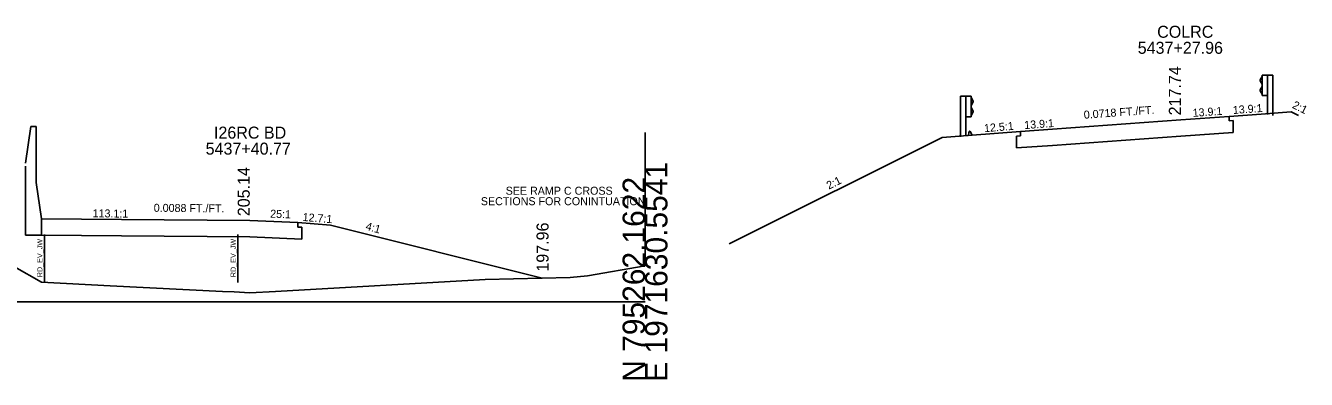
# Model space of a CAD drawing. Extents: x -161 to 1970889, y -4362 to 797231.
# Drawn here: x 1222.6 to 1382.7, y 3990.3 to 4034.5 of the extents above; entities that cross this region are included whole.
import ezdxf

# ---------------------------------------------------------------- set-up
doc = ezdxf.new("R2010")
doc.units = 0
for name, color, linetype in [('RD_GPK_XS_Cell', 7, 'Continuous'), ('RD_XS_Base', 7, 'Continuous'), ('RD_XS_CurbTop', 7, 'Continuous'), ('RD_XS_EarthShd', 7, 'Continuous'), ('RD_XS_ExGround', 7, 'Continuous'), ('RD_XS_EXWetland', 7, 'Continuous'), ('RD_XS_GR', 7, 'Continuous'), ('RD_XS_MedBWall', 7, 'Continuous'), ('RD_XS_Pave', 7, 'Continuous'), ('RD_XS_PaveShd', 7, 'Continuous'), ('RD_XS_TieSlope', 7, 'Continuous'), ('RD_XS_TX_Elev_PR', 7, 'Continuous'), ('RD_XS_TX_Misc', 7, 'Continuous'), ('RD_XS_TX_Notes', 7, 'Continuous'), ('RD_XS_TX_Profile', 7, 'Continuous'), ('RD_XS_TX_ShdSlope', 7, 'Continuous'), ('RD_XS_TX_Slope', 7, 'Continuous'), ('RD_XS_TX_Station', 7, 'Continuous')]:
    doc.layers.add(name, color=color, linetype=linetype)

msp = doc.modelspace()

# ---------------------------------------------------------------- linework, layer by layer
at = {"layer": 'RD_GPK_XS_Cell'}
msp.add_line((1150, 4000), (1300, 4000), dxfattribs=at)
at = {"layer": 'RD_XS_Base'}
for p, q in [((1372.99, 4022.61), (1372.99, 4023.17)), ((1346.92, 4020.73), (1346.92, 4021.29)), ((1373.49, 4022.65), (1372.99, 4022.61)), ((1373.49, 4021.17), (1373.49, 4022.65)), ((1346.42, 4020.7), (1346.92, 4020.73)), ((1346.42, 4019.22), (1346.42, 4020.7)), ((1350.93, 4019.54), (1366.97, 4020.7)), ((1366.97, 4020.7), (1373.49, 4021.17)), ((1350.93, 4019.54), (1346.42, 4019.22)), ((1224.58, 4009.81), (1224.58, 4010.37)), ((1256.59, 4009.34), (1256.59, 4009.9)), ((1257.09, 4009.32), (1256.59, 4009.34)), ((1257.09, 4007.84), (1257.09, 4009.32)), ((1234.58, 4008.24), (1224.58, 4008.33)), ((1234.58, 4008.24), (1250.59, 4008.1)), ((1250.59, 4008.1), (1257.09, 4007.84))]:
    msp.add_line(p, q, dxfattribs=at)
at = {"layer": 'RD_XS_CurbTop'}
for p, q in [((1340.9, 4020.81), (1340.65, 4021.27)), ((1340.43, 4020.78), (1340.49, 4021.21)), ((1340.9, 4020.81), (1340.43, 4020.78))]:
    msp.add_line(p, q, dxfattribs=at)
msp.add_ellipse((1340.58, 4021.19), major_axis=(0, 0.131), ratio=0.686, start_param=5.388101, end_param=7.661995, dxfattribs=at)
at = {"layer": 'RD_XS_EarthShd'}
for p, q in [((1372.99, 4023.17), (1377, 4023.46)), ((1346.92, 4021.29), (1340.9, 4020.81)), ((1256.59, 4009.9), (1260.67, 4009.58))]:
    msp.add_line(p, q, dxfattribs=at)
at = {"layer": 'RD_XS_ExGround'}
msp.add_lwpolyline([(1217.76, 4006.3), (1224.56, 4002.45), (1233.16, 4002.01), (1247.17, 4001.3), (1248.66, 4001.24), (1250.61, 4001.14), (1253.83, 4001.27), (1280.03, 4002.78), (1290.63, 4003.05), (1292.82, 4003.25), (1300, 4004.49)], dxfattribs=at)
at = {"layer": 'RD_XS_EXWetland'}
for p, q in [((1224.93, 4008.43), (1224.93, 4002.43)), ((1249.1, 4008.43), (1249.1, 4002.43))]:
    msp.add_line(p, q, dxfattribs=at)
at = {"layer": 'RD_XS_GR'}
for p, q in [((1377.15, 4028.17), (1376.88, 4027.73)), ((1376.88, 4027.73), (1376.88, 4027.62)), ((1377.15, 4028.33), (1377.81, 4028.33)), ((1377.15, 4025.76), (1377.15, 4028.33)), ((1377.81, 4028.33), (1378.48, 4028.33)), ((1377.81, 4028.33), (1377.81, 4023.39)), ((1378.48, 4028.33), (1378.48, 4023.28)), ((1376.88, 4027.62), (1377.15, 4027.18)), ((1376.88, 4026.48), (1377.15, 4026.92)), ((1376.88, 4026.37), (1376.88, 4026.48)), ((1377.15, 4025.93), (1376.88, 4026.37)), ((1340.09, 4025.69), (1339.42, 4025.69)), ((1339.42, 4025.69), (1339.42, 4020.63)), ((1340.75, 4025.69), (1340.09, 4025.69)), ((1340.09, 4025.69), (1340.09, 4020.75)), ((1340.75, 4023.12), (1340.75, 4025.69)), ((1340.75, 4025.53), (1341.02, 4025.09)), ((1341.02, 4024.98), (1340.75, 4024.54)), ((1341.02, 4025.09), (1341.02, 4024.98)), ((1377.15, 4025.76), (1377.81, 4025.76)), ((1340.75, 4023.12), (1340.09, 4023.12)), ((1341.02, 4023.83), (1340.75, 4024.27)), ((1340.75, 4023.28), (1341.02, 4023.72)), ((1341.02, 4023.72), (1341.02, 4023.83))]:
    msp.add_line(p, q, dxfattribs=at)
at = {"layer": 'RD_XS_MedBWall'}
for p, q in [((1222.58, 4017.34), (1223.25, 4021.89)), ((1223.91, 4021.89), (1223.25, 4021.89)), ((1223.91, 4021.89), (1223.91, 4014.92)), ((1222.58, 4016.94), (1222.58, 4008.33)), ((1224.58, 4010.37), (1223.91, 4014.92)), ((1224.58, 4010.37), (1224.58, 4008.33)), ((1224.58, 4008.33), (1222.58, 4008.33))]:
    msp.add_line(p, q, dxfattribs=at)
at = {"layer": 'RD_XS_Pave'}
for p, q in [((1350.93, 4021.58), (1366.97, 4022.74)), ((1234.58, 4010.28), (1250.59, 4010.14))]:
    msp.add_line(p, q, dxfattribs=at)
at = {"layer": 'RD_XS_PaveShd'}
for p, q in [((1366.97, 4022.74), (1372.99, 4023.17)), ((1350.93, 4021.58), (1346.92, 4021.29)), ((1234.58, 4010.28), (1224.58, 4010.37)), ((1250.59, 4010.14), (1256.59, 4009.9))]:
    msp.add_line(p, q, dxfattribs=at)
at = {"layer": 'RD_XS_TieSlope'}
for p, q in [((1377, 4023.46), (1380.76, 4023.73)), ((1380.76, 4023.73), (1381.68, 4023.27)), ((1337.14, 4020.51), (1310.53, 4007.25)), ((1340.9, 4020.81), (1337.14, 4020.51)), ((1260.67, 4009.58), (1287.14, 4002.96))]:
    msp.add_line(p, q, dxfattribs=at)
at = {"layer": 'RD_XS_TX_Notes'}
msp.add_line((1300, 4004.49), (1300, 4021.14), dxfattribs=at)

# ---------------------------------------------------------------- texts
at = {"layer": 'RD_GPK_XS_Cell'}
for s, p in [('E 1971630.5541', (1302.8, 3990)), ('N 795262.1622', (1300, 3990))]:
    msp.add_text(s, height=2.8, rotation=90, dxfattribs=at).set_placement(p)
at = {"layer": 'RD_XS_EXWetland'}
for p in [(1224.68, 4003.07), (1248.85, 4003.08)]:
    msp.add_text('RD_EV_JW', height=0.65, rotation=90, dxfattribs=at).set_placement(p)
at = {"layer": 'RD_XS_TX_Elev_PR'}
for s, p in [(' 217.74', (1366.97, 4022.74)), (' 205.14', (1250.59, 4010.14))]:
    msp.add_text(s, height=1.5, rotation=90, dxfattribs=at).set_placement(p)
at = {"layer": 'RD_XS_TX_Misc'}
msp.add_text('197.96', height=1.5, rotation=90, dxfattribs=at).set_placement((1287.94, 4003.77))
at = {"layer": 'RD_XS_TX_Notes'}
for s, p in [('SEE RAMP C CROSS ', (1282.58, 4013.38)), ('SECTIONS FOR CONINTUATION', (1279.48, 4012.07))]:
    msp.add_text(s, height=1, rotation=360, dxfattribs=at).set_placement(p)
at = {"layer": 'RD_XS_TX_Profile'}
msp.add_text('25:1', height=1, rotation=357.7097, dxfattribs=at).set_placement((1253.13, 4010.52))
at = {"layer": 'RD_XS_TX_ShdSlope'}
for s, rotation, p in [('13.9:1', 4.1099, (1373.5, 4023.46)), ('12.5:1', 4.5612, (1342.41, 4021.19)), ('12.7:1', 355.512, (1257.17, 4010.11))]:
    msp.add_text(s, height=1, rotation=rotation, dxfattribs=at).set_placement(p)
at = {"layer": 'RD_XS_TX_Slope'}
for s, rotation, p in [('0.0718 FT./FT.', 4.1093, (1354.87, 4022.87)), ('2:1', 333.4957, (1380.81, 4024.26)), ('13.9:1', 4.1099, (1368.48, 4023.1)), ('13.9:1', 4.1093, (1347.43, 4021.58)), ('2:1', 26.5011, (1322.98, 4014.01)), ('0.0088 FT./FT.', 359.4933, (1238.59, 4011.25)), ('113.1:1', 359.4933, (1230.95, 4010.56)), ('4:1', 344.1175, (1265, 4009.03))]:
    msp.add_text(s, height=1, rotation=rotation, dxfattribs=at).set_placement(p)
at = {"layer": 'RD_XS_TX_Station'}
for s, p in [('COLRC', (1364.01, 4032.99)), ('5437+27.96', (1361.58, 4030.99)), ('I26RC BD', (1246.12, 4020.39)), ('5437+40.77', (1245.08, 4018.39))]:
    msp.add_text(s, height=1.5, dxfattribs=at).set_placement(p)

doc.saveas('drawing.dxf')
